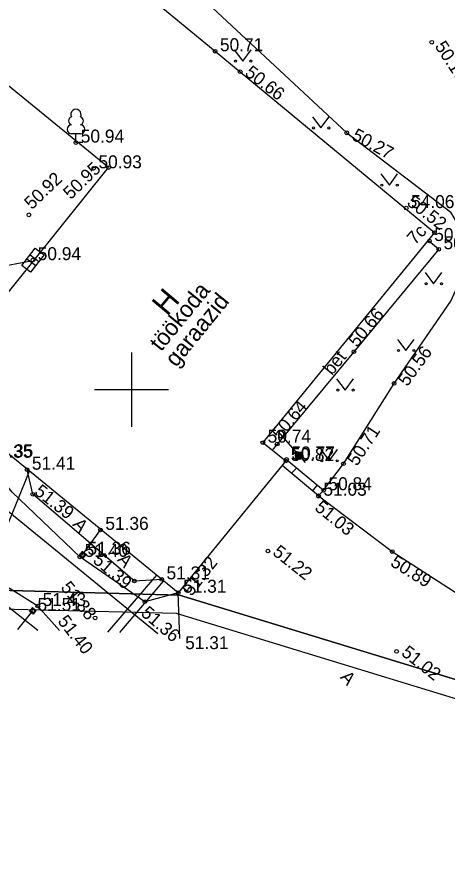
# Model space of a CAD drawing. Extents: x 640876 to 641418, y 6455595 to 6456085.
# Drawn here: x 641143.81 to 641167.04, y 6455774.33 to 6455820.12 of the extents above; entities that cross this region are included whole.
import ezdxf

# ---------------------------------------------------------------- set-up
doc = ezdxf.new("R2010")
doc.units = 0
for name, color, linetype in [('AED', 7, 'Continuous'), ('HALJASTUS', 7, 'Continuous'), ('HOONE', 7, 'Continuous'), ('HOONEDET', 7, 'Continuous'), ('KORGUS', 7, 'Continuous'), ('KTRASS', 7, 'Continuous'), ('MOOTKORG', 7, 'Continuous'), ('MOOTMPUNKT', 7, 'Continuous'), ('MOOTPIIR', 7, 'Continuous'), ('MPOHULIIN', 7, 'Continuous'), ('PIIR', 7, 'Continuous'), ('POST', 7, 'Continuous'), ('PUU', 7, 'Continuous'), ('SIOHULIIN', 7, 'Continuous'), ('SITRASS', 7, 'Continuous'), ('TEE', 7, 'Continuous'), ('TTRASS', 7, 'Continuous'), ('VORK', 7, 'Continuous'), ('VTRASS', 7, 'Continuous')]:
    doc.layers.add(name, color=color, linetype=linetype)

msp = doc.modelspace()

# ---------------------------------------------------------------- linework, layer by layer
at = {"layer": 'AED'}
for p, q in [((641158.92, 6455795.778), (641158.638, 6455795.488)), ((641160.03, 6455794.855), (641159.774, 6455794.543)), ((641147.326, 6455791.26), (641147.17, 6455791.064)), ((641147.366, 6455790.908), (641147.17, 6455791.064)), ((641147.522, 6455791.104), (641147.326, 6455791.26)), ((641147.522, 6455791.104), (641147.366, 6455790.908)), ((641144.638, 6455788.233), (641144.482, 6455788.037)), ((641144.834, 6455788.077), (641144.638, 6455788.233)), ((641144.678, 6455787.881), (641144.482, 6455788.037)), ((641144.834, 6455788.077), (641144.678, 6455787.881))]:
    msp.add_line(p, q, dxfattribs=at)
for points in [[(641158.318, 6455796.163), (641158.373, 6455796.233), (641160.373, 6455794.57), (641160.099, 6455794.273), (641158.137, 6455795.904)], [(641147.35, 6455791.081), (641147.355, 6455791.087), (641148.336, 6455792.452)], [(641143.857, 6455787.054), (641144.657, 6455788.056)]]:
    msp.add_lwpolyline(points, dxfattribs=at)
at = {"layer": 'HALJASTUS'}
for p, q in [((641155.545, 6455818.346), (641156.009, 6455817.74)), ((641156.009, 6455817.74), (641156.454, 6455818.346)), ((641159.765, 6455814.732), (641160.228, 6455814.125)), ((641160.228, 6455814.125), (641160.674, 6455814.732)), ((641163.46, 6455811.642), (641163.923, 6455811.035)), ((641163.923, 6455811.035), (641164.369, 6455811.642)), ((641165.851, 6455806.325), (641166.315, 6455805.718)), ((641166.315, 6455805.718), (641166.76, 6455806.325)), ((641164.358, 6455802.714), (641164.821, 6455802.107)), ((641164.821, 6455802.107), (641165.267, 6455802.714)), ((641161.076, 6455800.585), (641161.539, 6455799.978)), ((641161.539, 6455799.978), (641161.985, 6455800.585)), ((641160.214, 6455796.769), (641160.677, 6455796.162)), ((641160.677, 6455796.162), (641161.123, 6455796.769))]:
    msp.add_line(p, q, dxfattribs=at)
for centre in [(641155.608, 6455817.74), (641156.436, 6455817.74), (641159.827, 6455814.125), (641160.656, 6455814.125), (641163.522, 6455811.035), (641164.351, 6455811.035), (641165.914, 6455805.718), (641166.742, 6455805.718), (641164.42, 6455802.107), (641165.249, 6455802.107), (641161.138, 6455799.978), (641161.967, 6455799.978), (641160.276, 6455796.162), (641161.105, 6455796.162)]:
    msp.add_circle(centre, 0.055, dxfattribs=at)
at = {"layer": 'HOONE'}
msp.add_lwpolyline([(641139.149, 6455869.673), (641123.276, 6455850.742), (641124.076, 6455850.041), (641120.776, 6455845.978), (641123.157, 6455844.065), (641125.741, 6455841.899), (641129.074, 6455839.178), (641138.729, 6455831.239), (641154.511, 6455818.271), (641155.863, 6455817.162), (641166.356, 6455808.477), (641157.088, 6455797.138), (641158.337, 6455796.148), (641152.522, 6455789.036), (641139.095, 6455799.993), (641148.747, 6455811.989), (641140.492, 6455818.73), (641127.295, 6455829.597), (641115.375, 6455839.33), (641112.285, 6455835.53)], dxfattribs=at)
at = {"layer": 'KORGUS'}
for centre in [(641166.21, 6455818.757), (641155.863, 6455817.162), (641161.624, 6455813.864), (641148.747, 6455811.989), (641144.452, 6455809.436), (641166.356, 6455808.477), (641162.01, 6455802.043), (641164.176, 6455800.333), (641157.862, 6455797.064), (641161.446, 6455796), (641144.657, 6455794.35), (641160.101, 6455794.243), (641157.36, 6455791.288), (641164.082, 6455791.256), (641150.151, 6455789.668), (641152.523, 6455789.036), (641150.717, 6455788.551), (641148.025, 6455787.673), (641164.315, 6455785.865)]:
    msp.add_circle(centre, 0.1, dxfattribs=at)
at = {"layer": 'KTRASS'}
msp.add_line((641131.956, 6455797.189), (641144.933, 6455787.023), dxfattribs=at)
at = {"layer": 'MOOTMPUNKT'}
for centre in [(641154.511, 6455818.271), (641146.993, 6455813.338), (641147.949, 6455811.949), (641164.834, 6455809.8), (641166.085, 6455808.023), (641166.59, 6455807.58), (641144.667, 6455806.991), (641157.088, 6455797.138), (641158.337, 6455796.148), (641158.373, 6455796.233), (641144.353, 6455795.677), (641160.373, 6455794.57), (641160.099, 6455794.273), (641148.319, 6455792.429), (641147.201, 6455790.973), (641147.355, 6455791.087), (641151.626, 6455789.757), (641152.522, 6455789.036), (641144.934, 6455788.318), (641144.658, 6455788.057)]:
    msp.add_circle(centre, 0.1, dxfattribs=at)
at = {"layer": 'MOOTPIIR'}
msp.add_lwpolyline([(641060.916, 6455895.936), (641100.061, 6455950.482), (641099.586, 6455952.159), (641069.132, 6455984.035), (641066.132, 6455988.623), (641076.463, 6456005.049), (641230.642, 6456010.048), (641237.36, 6455995.24), (641237.24, 6455992.81), (641236.258, 6455990.888), (641229.041, 6455971.315), (641203.026, 6455909.57), (641225.257, 6455906.847), (641239.512, 6455898.491), (641200.195, 6455851.697), (641192.016, 6455859.099), (641169.785, 6455829.138), (641192.025, 6455807.568), (641252.96, 6455758.075), (641231.388, 6455736.74), (641191.474, 6455775.975), (641152.419, 6455787.914), (641136.351, 6455788.307), (641049.066, 6455856.043)], dxfattribs=at)
at = {"layer": 'MPOHULIIN'}
for p, q in [((641144.706, 6455806.966), (641144.706, 6455806.966)), ((641144.46, 6455806.919), (641142.251, 6455806.494))]:
    msp.add_line(p, q, dxfattribs=at)
at = {"layer": 'PIIR'}
for points in [[(641216.67, 6455752.61), (641192, 6455776.86), (641152.58, 6455788.91), (641136.9, 6455789.33), (641119.28, 6455802.72), (641101.72, 6455816.27), (641098.61, 6455818.83), (641124.03, 6455849.78), (641139.51, 6455868.99), (641157, 6455885.69), (641191.84, 6455860.59), (641168.46, 6455829.03), (641191.37, 6455806.79), (641234.69, 6455771.62)], [(641216.67, 6455752.61), (641182.28, 6455716.38), (641177.47, 6455716.39), (641127.83, 6455755.09), (641138.89, 6455768.28), (641129.48, 6455779.82), (641136.9, 6455789.33), (641152.58, 6455788.91), (641192, 6455776.86)]]:
    msp.add_lwpolyline(points, close=True, dxfattribs=at)
at = {"layer": 'POST'}
for p, q in [((641144.348, 6455807.067), (641144.819, 6455806.701)), ((641144.515, 6455807.281), (641144.986, 6455806.915))]:
    msp.add_line(p, q, dxfattribs=at)
msp.add_lwpolyline([(641144.065, 6455806.703), (641144.798, 6455807.646), (641145.269, 6455807.279), (641144.536, 6455806.336)], close=True, dxfattribs=at)
at = {"layer": 'PUU'}
for p, q in [((641147.233, 6455813.813), (641146.753, 6455813.813)), ((641146.993, 6455813.338), (641146.993, 6455813.813)), ((641147.373, 6455813.338), (641146.993, 6455813.338))]:
    msp.add_line(p, q, dxfattribs=at)
for centre, radius, start, end in [((641146.823, 6455814.511), 0.233, 109.0217, 253.1415), ((641146.993, 6455814.858), 0.277, 332.5799, 207.4201), ((641147.163, 6455814.511), 0.233, 286.8508, 70.9859), ((641146.756, 6455814.05), 0.238, 90.0016, 269.3953), ((641147.23, 6455814.05), 0.238, 270.6047, 89.9984)]:
    msp.add_arc(centre, radius, start, end, dxfattribs=at)
at = {"layer": 'SIOHULIIN'}
for p, q in [((641157.736, 6455797.931), (641157.736, 6455797.931)), ((641157.901, 6455797.743), (641159.38, 6455796.059))]:
    msp.add_line(p, q, dxfattribs=at)
for radius in [0.199, 0.19, 0.18, 0.171, 0.162, 0.152, 0.143, 0.133, 0.124, 0.114, 0.105, 0.0953, 0.0858, 0.0763, 0.0669, 0.0574, 0.0479, 0.0385, 0.029, 0.0195, 0.0101, 0.00061]:
    msp.add_circle((641159.052, 6455796.432), radius, dxfattribs=at)
at = {"layer": 'SITRASS'}
msp.add_lwpolyline([(641141.028, 6455787.135), (641144.48, 6455795.599)], dxfattribs=at)
at = {"layer": 'TEE'}
for points in [[(641159.238, 6455874.204), (641158.276, 6455874.888), (641154.5, 6455876.457), (641151.524, 6455876.394), (641148.985, 6455874.775), (641145.506, 6455872.238), (641137.229, 6455865.803), (641131.822, 6455858.971), (641127.09, 6455853.908), (641125.918, 6455849.675), (641127.928, 6455844.823), (641130.752, 6455841.149), (641137.584, 6455833.839), (641144.779, 6455828.121), (641152.823, 6455822.069), (641161.624, 6455813.864), (641167.235, 6455809.577)], [(641146.099, 6455786.99), (641144.934, 6455788.318), (641140.92, 6455790.807), (641133.213, 6455794.381), (641127.043, 6455799.198), (641121.299, 6455804.336), (641115.306, 6455808.241), (641107.025, 6455814.477), (641099.665, 6455819.667)], [(641160.373, 6455794.57), (641161.446, 6455796), (641164.176, 6455800.333), (641167.241, 6455804.782), (641168.195, 6455806.885), (641168.038, 6455808.236), (641167.235, 6455809.577)], [(641166.027, 6455808.074), (641166.59, 6455807.58), (641162.01, 6455802.043), (641157.862, 6455797.064), (641157.599, 6455796.733)], [(641152.522, 6455789.036), (641150.717, 6455788.551), (641147.201, 6455790.973), (641143.551, 6455794.471), (641142.04, 6455796.323)], [(641151.626, 6455789.757), (641150.151, 6455789.668), (641144.657, 6455794.35), (641144.353, 6455795.677)], [(641160.099, 6455794.273), (641164.082, 6455791.256), (641169.355, 6455787.863), (641187.027, 6455774.627)], [(641152.611, 6455786.567), (641152.523, 6455789.036)]]:
    msp.add_lwpolyline(points, dxfattribs=at)
at = {"layer": 'TTRASS'}
for points in [[(641148.721, 6455786.915), (641151.358, 6455789.986)], [(641149.364, 6455786.897), (641151.746, 6455789.669)]]:
    msp.add_lwpolyline(points, dxfattribs=at)
at = {"layer": 'VORK'}
for p, q in [((641150, 6455802), (641150, 6455798)), ((641148, 6455800), (641152, 6455800))]:
    msp.add_line(p, q, dxfattribs=at)
at = {"layer": 'VTRASS'}
msp.add_lwpolyline([(641123.713, 6455832.522), (641112.411, 6455818.681), (641151.409, 6455786.838)], dxfattribs=at)

# ---------------------------------------------------------------- texts
at = {"layer": 'HOONE'}
for s, height, rotation, p in [('7c', 0.7, 46.9227, (641165.311, 6455807.783)), ('töökoda ', 0.9, 50.8282, (641151.588, 6455802.012)), ('H', 1.2, 50.0136, (641151.921, 6455803.919)), ('garaazid', 0.9, 50.8282, (641152.409, 6455801.169))]:
    msp.add_text(s, height=height, rotation=rotation, dxfattribs=at).set_placement(p)
at = {"layer": 'HOONEDET'}
msp.add_text('bet', height=0.7, rotation=51.2682, dxfattribs=at).set_placement((641160.825, 6455800.733))
at = {"layer": 'KORGUS'}
for s, rotation, p in [(' 50.16', 303.0557, (641166.21, 6455818.757)), (' 50.66', 322.343, (641155.863, 6455817.162)), (' 50.27', 331.2831, (641161.616, 6455813.656)), (' 50.95', 44.1602, (641146.525, 6455810.046)), (' 50.92', 43.718, (641144.424, 6455809.505)), (' 50.52', 322.2205, (641164.613, 6455810.167)), (' 50.66', 50.2126, (641162.01, 6455802.043)), (' 50.56', 54.0891, (641164.743, 6455799.922)), (' 50.64', 49.8648, (641157.862, 6455797.064)), (' 50.71', 56.4894, (641162.03, 6455795.614)), (' 51.39', 321.936, (641144.491, 6455794.557)), (' 51.03', 320.9601, (641159.641, 6455793.705)), (' 51.22', 321.5682, (641157.36, 6455791.288)), (' 51.39', 318.7964, (641147.668, 6455790.883)), (' 51.32', 51.7357, (641153.072, 6455788.603)), (' 50.89', 328.011, (641163.711, 6455790.662)), (' 51.38', 309.5489, (641145.967, 6455789.498)), (' 51.36', 319.1945, (641150.26, 6455788.021)), (' 51.40', 308.2889, (641145.81, 6455787.69)), (' 51.02', 321.6081, (641164.315, 6455785.865))]:
    msp.add_text(s, height=0.7, rotation=rotation, dxfattribs=at).set_placement(p)
at = {"layer": 'MOOTKORG'}
for s, p in [(' 50.71', (641154.511, 6455818.271)), (' 50.94', (641146.993, 6455813.338)), (' 50.93', (641147.949, 6455811.949)), (' 54.06', (641164.834, 6455809.8)), (' 50.62', (641166.085, 6455808.023)), (' 50.54', (641166.59, 6455807.58)), (' 50.94', (641144.667, 6455806.991)), (' 50.74', (641157.088, 6455797.138)), (' 51.35', (641142.04, 6455796.323)), (' 51.35', (641142.084, 6455796.351)), (' 50.77', (641158.373, 6455796.233)), (' 50.82', (641158.337, 6455796.148)), (' 51.41', (641144.353, 6455795.677)), (' 50.84', (641160.373, 6455794.57)), (' 51.03', (641160.099, 6455794.273)), (' 51.36', (641148.319, 6455792.429)), (' 51.40', (641147.201, 6455790.973)), (' 51.36', (641147.355, 6455791.087)), (' 51.31', (641151.626, 6455789.757)), (' 51.31', (641152.522, 6455789.036)), (' 51.51', (641144.658, 6455788.057)), (' 51.43', (641144.934, 6455788.318)), (' 51.31', (641152.632, 6455785.989))]:
    msp.add_text(s, height=0.7, dxfattribs=at).set_placement(p)
at = {"layer": 'TEE'}
for p in [(641146.776, 6455792.698), (641149.19, 6455790.793), (641161.231, 6455784.449)]:
    msp.add_text('A', height=0.7, rotation=311.4262, dxfattribs=at).set_placement(p)

doc.saveas('drawing.dxf')
